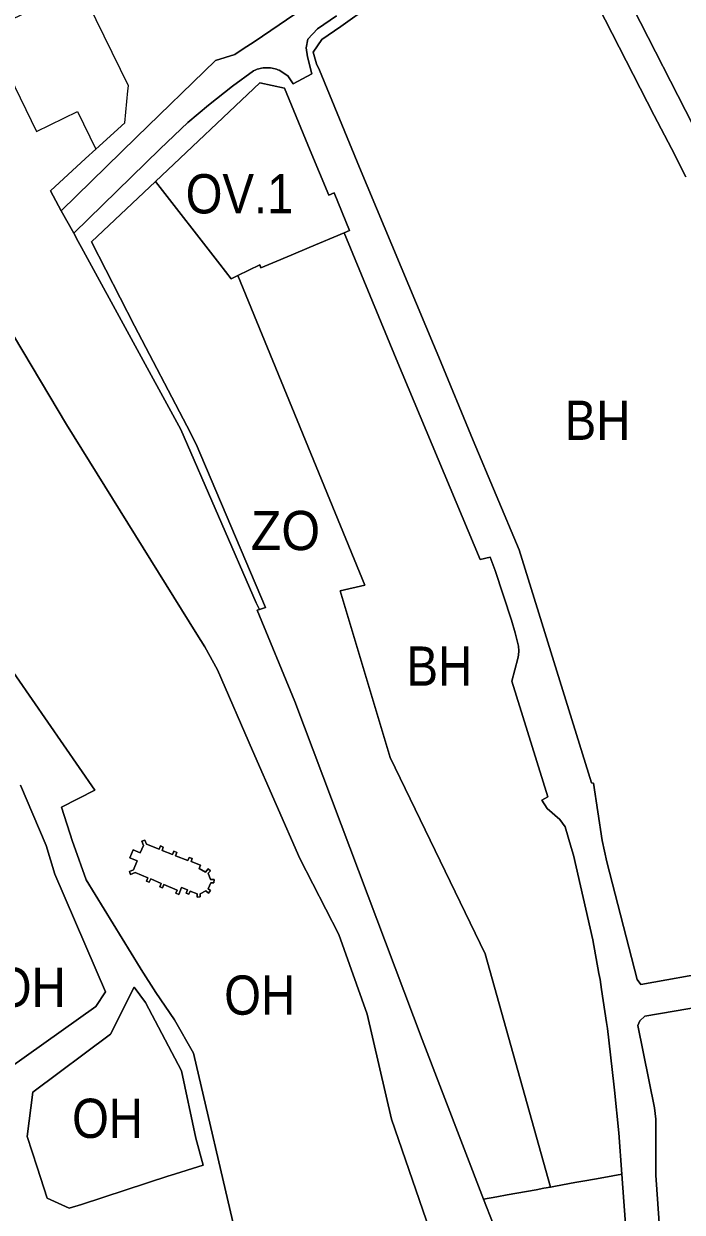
# Model space of a CAD drawing. Extents: x -650451 to -642268, y -1075216 to -1066610.
# Drawn here: x -647556.9 to -647355.8, y -1071464 to -1071100.7 of the extents above; entities that cross this region are included whole.
import ezdxf

# ---------------------------------------------------------------- set-up
doc = ezdxf.new("R2010")
doc.units = 0
doc.header["$LTSCALE"] = 4.8
for name, color, linetype, lineweight in [('1', 7, 'Continuous', 13), ('10', 7, 'Continuous', 13), ('11', 7, 'Continuous', 13), ('15', 7, 'Continuous', 13), ('24', 7, 'Continuous', 13), ('25', 7, 'Continuous', 13), ('42', 7, 'Continuous', 13)]:
    doc.layers.add(name, color=color, linetype=linetype, lineweight=lineweight)
doc.layers.add('62', color=7, linetype='Continuous')

msp = doc.modelspace()

# ---------------------------------------------------------------- linework, layer by layer
at = {"layer": '1'}
for points in [[(-647316.07, -1071202.91), (-647370.76, -1071095.88), (-647373.86, -1071090.07), (-647383.43, -1071070.95), (-647388.51, -1071058.82), (-647387.82, -1071056.14), (-647386.3, -1071054.58), (-647349.67, -1071030.64)], [(-647389.98, -1071078.54), (-647364.3, -1071128.77), (-647359.04, -1071138.83), (-647354.68, -1071147.49)], [(-647345.67, -1071390.27), (-647368.38, -1071394.35), (-647369.51, -1071392.87), (-647378.79, -1071356.84), (-647380.17, -1071350.38), (-647382.83, -1071332.82), (-647383.52, -1071332.79), (-647405.59, -1071261.54), (-647419.59, -1071228.11), (-647430.16, -1071202.64), (-647431.77, -1071198.79), (-647454.33, -1071144.64), (-647466.6, -1071114.88), (-647467.47, -1071112.93), (-647468.47, -1071109.42), (-647465.83, -1071105.54), (-647460.06, -1071101.57), (-647442.36, -1071088.82)], [(-647491.56, -1071177.65), (-647484.85, -1071174.37), (-647484.47, -1071175.32), (-647480.78, -1071173.77), (-647475.25, -1071171.44), (-647469.69, -1071169.11), (-647458.99, -1071164.62)], [(-647458.99, -1071164.62), (-647443.1, -1071203.11), (-647417.48, -1071264.44), (-647414.45, -1071263.72), (-647412.92, -1071267.86), (-647407.95, -1071282.98), (-647406.83, -1071286.84), (-647405.81, -1071290.99), (-647405.67, -1071292.42), (-647405.81, -1071293.71), (-647406, -1071294.73), (-647407.77, -1071301.63), (-647396.78, -1071337.03), (-647398.69, -1071338), (-647397.07, -1071340.54), (-647393.18, -1071343.93), (-647391.57, -1071346.17), (-647389.7, -1071352.48), (-647389.02, -1071354.89), (-647383.11, -1071380.7), (-647381.2, -1071391.04), (-647380.88, -1071392.81), (-647380.41, -1071395.94), (-647378.88, -1071406.02), (-647378.64, -1071407.86), (-647376.66, -1071424.88), (-647376.42, -1071426.67), (-647375.13, -1071439.72), (-647374.2, -1071452.36)], [(-647396.02, -1071456.32), (-647415.97, -1071385.01), (-647445, -1071324.99), (-647460.28, -1071274.02), (-647452.69, -1071272.32), (-647491.56, -1071177.65)], [(-647353.95, -1071567.53), (-647356.2, -1071564.75), (-647356.91, -1071554.11), (-647357.15, -1071550.44), (-647359.03, -1071522.12), (-647359.38, -1071516.88), (-647363.86, -1071452.66), (-647363.83, -1071435.52), (-647364.26, -1071432.14), (-647369.34, -1071406.92), (-647368.74, -1071405.48), (-647367.18, -1071404.12), (-647349.29, -1071400.99)], [(-647374.2, -1071452.36), (-647379.73, -1071453.36), (-647382.59, -1071453.88), (-647385.49, -1071454.41), (-647388.54, -1071454.96), (-647394.45, -1071456.04), (-647396.02, -1071456.32)]]:
    msp.add_lwpolyline(points, dxfattribs=at)
at = {"layer": '10'}
for points in [[(-647565.22, -1071187.4), (-647543.83, -1071223.23), (-647504.01, -1071287.34), (-647501.59, -1071291.15), (-647497.77, -1071298.19), (-647487.02, -1071322.83), (-647472.58, -1071355.91), (-647460.71, -1071379.08), (-647451.96, -1071403.5), (-647444.55, -1071435.57), (-647430.76, -1071475.77), (-647422.68, -1071509.72), (-647416, -1071538.22)], [(-647492.3, -1071470), (-647505.11, -1071415.37), (-647510.84, -1071405.24), (-647516.55, -1071396.79), (-647521.06, -1071389.76), (-647521.32, -1071389.29), (-647537.84, -1071362.41), (-647541.66, -1071351.76), (-647542.01, -1071350.72), (-647545.42, -1071340.16), (-647535.19, -1071335), (-647568.83, -1071286.51), (-647592.65, -1071252.72), (-647607.49, -1071231.68), (-647608.09, -1071228.7), (-647608.04, -1071225.7), (-647607.11, -1071222.78), (-647605.5, -1071220.17)], [(-647557.95, -1071333.44), (-647554.18, -1071342.3), (-647550.12, -1071351.87), (-647547.43, -1071360.71), (-647531.93, -1071396.68), (-647534.94, -1071401.09), (-647561.38, -1071419.94)]]:
    msp.add_lwpolyline(points, dxfattribs=at)
for points in [[(-647523.37, -1071359.34), (-647524.63, -1071359.81), (-647524.28, -1071360.72), (-647522.92, -1071360.2), (-647519.05, -1071361.79), (-647519.46, -1071362.76), (-647518.59, -1071363.1), (-647518.1, -1071362.12), (-647514.97, -1071363.49), (-647515.39, -1071364.49), (-647514.5, -1071364.86), (-647514.09, -1071363.85), (-647510.06, -1071365.53), (-647510.48, -1071366.51), (-647509.58, -1071366.9), (-647508.73, -1071364.78), (-647506.94, -1071365.49), (-647507.29, -1071366.45), (-647506.47, -1071366.76), (-647506.04, -1071365.82), (-647503.99, -1071366.66), (-647503.96, -1071367.67), (-647502.98, -1071367.63), (-647503.01, -1071366.67), (-647501.29, -1071365.73), (-647500.51, -1071366.44), (-647499.87, -1071365.69), (-647500.55, -1071365.1), (-647499.81, -1071363.3), (-647498.84, -1071363.29), (-647498.8, -1071362.34), (-647499.87, -1071362.28), (-647500.57, -1071360.36), (-647499.86, -1071359.67), (-647500.55, -1071359.01), (-647501.43, -1071360.01), (-647503.33, -1071358.95), (-647502.94, -1071357.95), (-647505.79, -1071356.81), (-647505.45, -1071355.86), (-647506.38, -1071355.53), (-647506.75, -1071356.51), (-647510.59, -1071355.01), (-647510.18, -1071354.02), (-647511.1, -1071353.63), (-647511.51, -1071354.65), (-647514.67, -1071353.39), (-647514.29, -1071352.36), (-647515.19, -1071352.03), (-647515.6, -1071353), (-647519.45, -1071351.47), (-647519.95, -1071350.22), (-647520.85, -1071350.56), (-647520.37, -1071351.85), (-647521.31, -1071354.19), (-647523.5, -1071353.25), (-647524.47, -1071355.64), (-647522.28, -1071356.63)], [(-647523.23, -1071395.17), (-647519.72, -1071399.92), (-647508.69, -1071420.74), (-647504.34, -1071441.33), (-647502.09, -1071449.64), (-647512.23, -1071452.75), (-647512.62, -1071452.86), (-647539.31, -1071461.66), (-647543.05, -1071462.76), (-647549.73, -1071459.73), (-647552.85, -1071450.23), (-647555.92, -1071440.87), (-647554.16, -1071427.31), (-647530.41, -1071409.54)]]:
    msp.add_lwpolyline(points, close=True, dxfattribs=at)
at = {"layer": '11'}
for points in [[(-647516.65, -1071148.87), (-647484.84, -1071118.8), (-647477.3, -1071120.38), (-647469.39, -1071139.47), (-647463.76, -1071153.08), (-647462.13, -1071152.39), (-647457.39, -1071163.94), (-647458.99, -1071164.62)], [(-647491.56, -1071177.65), (-647493.58, -1071178.64), (-647497.03, -1071174.18), (-647516.65, -1071148.87)], [(-647458.99, -1071164.62), (-647469.69, -1071169.11), (-647475.25, -1071171.44), (-647480.78, -1071173.77), (-647484.47, -1071175.32), (-647484.85, -1071174.37), (-647491.56, -1071177.65)]]:
    msp.add_lwpolyline(points, dxfattribs=at)
msp.add_lwpolyline([(-647523.37, -1071359.34), (-647522.28, -1071356.63), (-647524.47, -1071355.64), (-647523.5, -1071353.25), (-647521.31, -1071354.19), (-647520.37, -1071351.85), (-647520.85, -1071350.56), (-647519.95, -1071350.22), (-647519.45, -1071351.47), (-647515.6, -1071353), (-647515.19, -1071352.03), (-647514.29, -1071352.36), (-647514.67, -1071353.39), (-647511.51, -1071354.65), (-647511.1, -1071353.63), (-647510.18, -1071354.02), (-647510.59, -1071355.01), (-647506.75, -1071356.51), (-647506.38, -1071355.53), (-647505.45, -1071355.86), (-647505.79, -1071356.81), (-647502.94, -1071357.95), (-647503.33, -1071358.95), (-647501.43, -1071360.01), (-647500.55, -1071359.01), (-647499.86, -1071359.67), (-647500.57, -1071360.36), (-647499.87, -1071362.28), (-647498.8, -1071362.34), (-647498.84, -1071363.29), (-647499.81, -1071363.3), (-647500.55, -1071365.1), (-647499.87, -1071365.69), (-647500.51, -1071366.44), (-647501.29, -1071365.73), (-647503.01, -1071366.67), (-647502.98, -1071367.63), (-647503.96, -1071367.67), (-647503.99, -1071366.66), (-647506.04, -1071365.82), (-647506.47, -1071366.76), (-647507.29, -1071366.45), (-647506.94, -1071365.49), (-647508.73, -1071364.78), (-647509.58, -1071366.9), (-647510.48, -1071366.51), (-647510.06, -1071365.53), (-647514.09, -1071363.85), (-647514.5, -1071364.86), (-647515.39, -1071364.49), (-647514.97, -1071363.49), (-647518.1, -1071362.12), (-647518.59, -1071363.1), (-647519.46, -1071362.76), (-647519.05, -1071361.79), (-647522.92, -1071360.2), (-647524.28, -1071360.72), (-647524.63, -1071359.81)], close=True, dxfattribs=at)
at = {"layer": '15'}
for points in [[(-647364.66, -1071006.25), (-647361.42, -1071004.71), (-647356.96, -1071010.82), (-647356.47, -1071014.98), (-647356.62, -1071017.06), (-647361.56, -1071021.28), (-647392.4, -1071042.15), (-647410.1, -1071054.18), (-647415.14, -1071057.61), (-647469.06, -1071094.28), (-647486.58, -1071106.19), (-647489.86, -1071108.38), (-647492.4, -1071110.08), (-647498.37, -1071111.95), (-647522.5, -1071135.41), (-647545.47, -1071157.86)], [(-647349.67, -1071030.64), (-647386.3, -1071054.58), (-647387.82, -1071056.14), (-647388.51, -1071058.82), (-647383.43, -1071070.95), (-647373.86, -1071090.07), (-647370.76, -1071095.88), (-647316.07, -1071202.91)], [(-647354.68, -1071147.49), (-647359.04, -1071138.83), (-647364.3, -1071128.77), (-647389.98, -1071078.54)], [(-647534.851, -1071139.015), (-647526.04, -1071130.94), (-647525.1, -1071121.25), (-647524.95, -1071119.68), (-647539.817, -1071089.199)], [(-647442.36, -1071088.82), (-647460.06, -1071101.57), (-647465.83, -1071105.54), (-647468.47, -1071109.42), (-647467.47, -1071112.93), (-647466.6, -1071114.88), (-647454.33, -1071144.64), (-647431.77, -1071198.79), (-647430.16, -1071202.64), (-647419.59, -1071228.11), (-647405.59, -1071261.54), (-647383.52, -1071332.79), (-647382.83, -1071332.82), (-647380.17, -1071350.38), (-647378.79, -1071356.84), (-647369.51, -1071392.87), (-647368.38, -1071394.35), (-647345.67, -1071390.27)], [(-647541.66, -1071164.75), (-647515.26, -1071138.89), (-647506.78, -1071130.92), (-647500.44, -1071125.54), (-647493.16, -1071119.77), (-647486.76, -1071115.13), (-647486, -1071114.76), (-647485.58, -1071114.61), (-647485.149, -1071114.479), (-647484.709, -1071114.368), (-647484.262, -1071114.278), (-647483.809, -1071114.209), (-647483.352, -1071114.162), (-647482.892, -1071114.138), (-647482.43, -1071114.137), (-647481.969, -1071114.158), (-647481.51, -1071114.201), (-647481.055, -1071114.267), (-647480.605, -1071114.355), (-647480.163, -1071114.464), (-647479.728, -1071114.593), (-647479.304, -1071114.742), (-647478.89, -1071114.91), (-647476.29, -1071116.6), (-647474.6, -1071119.05), (-647468.9, -1071115.97), (-647470.21, -1071110.77), (-647470.6, -1071108.01), (-647470.17, -1071105.39), (-647467.21, -1071102.22), (-647461.39, -1071098.23)], [(-647458.99, -1071164.62), (-647457.39, -1071163.94), (-647462.13, -1071152.39), (-647463.76, -1071153.08), (-647469.39, -1071139.47), (-647477.3, -1071120.38), (-647484.84, -1071118.8), (-647516.65, -1071148.87)], [(-647545.47, -1071157.86), (-647548.7, -1071151.72), (-647538.02, -1071141.92), (-647534.851, -1071139.015)], [(-647516.65, -1071148.87), (-647536.2, -1071167.35), (-647523.09, -1071193.08), (-647507.14, -1071223.62), (-647504.27, -1071229.17), (-647483.04, -1071279.11), (-647484.9, -1071279.73)], [(-647484.9, -1071279.73), (-647485.9, -1071277.7), (-647508.98, -1071224.74), (-647539.25, -1071169.11), (-647540.27, -1071167.26), (-647541.66, -1071164.75)], [(-647374.2, -1071452.36), (-647375.13, -1071439.72), (-647376.42, -1071426.67), (-647376.66, -1071424.88), (-647378.64, -1071407.86), (-647378.88, -1071406.02), (-647380.41, -1071395.94), (-647380.88, -1071392.81), (-647381.2, -1071391.04), (-647383.11, -1071380.7), (-647389.02, -1071354.89), (-647389.7, -1071352.48), (-647391.57, -1071346.17), (-647393.18, -1071343.93), (-647397.07, -1071340.54), (-647398.69, -1071338), (-647396.78, -1071337.03), (-647407.77, -1071301.63), (-647406, -1071294.73), (-647405.81, -1071293.71), (-647405.67, -1071292.42), (-647405.81, -1071290.99), (-647406.83, -1071286.84), (-647407.95, -1071282.98), (-647412.92, -1071267.86), (-647414.45, -1071263.72), (-647417.48, -1071264.44), (-647443.1, -1071203.11), (-647458.99, -1071164.62)], [(-647605.5, -1071220.17), (-647607.11, -1071222.78), (-647608.04, -1071225.7), (-647608.09, -1071228.7), (-647607.49, -1071231.68), (-647592.65, -1071252.72), (-647568.83, -1071286.51), (-647535.19, -1071335), (-647545.42, -1071340.16), (-647542.01, -1071350.72), (-647541.66, -1071351.76), (-647537.84, -1071362.41), (-647521.32, -1071389.29), (-647521.06, -1071389.76), (-647516.55, -1071396.79), (-647510.84, -1071405.24), (-647505.11, -1071415.37), (-647492.3, -1071470), (-647498.8, -1071471.94)], [(-647561.38, -1071419.94), (-647534.94, -1071401.09), (-647531.93, -1071396.68), (-647547.43, -1071360.71), (-647550.12, -1071351.87), (-647554.18, -1071342.3), (-647557.95, -1071333.44)], [(-647349.29, -1071400.99), (-647367.18, -1071404.12), (-647368.74, -1071405.48), (-647369.34, -1071406.92), (-647364.26, -1071432.14), (-647363.83, -1071435.52), (-647363.86, -1071452.66), (-647359.38, -1071516.88), (-647359.03, -1071522.12), (-647357.15, -1071550.44), (-647356.91, -1071554.11), (-647356.2, -1071564.75), (-647353.95, -1071567.53)], [(-647377.13, -1071562.56), (-647365.91, -1071564.81), (-647368.26, -1071532.99), (-647374.2, -1071452.36)]]:
    msp.add_lwpolyline(points, dxfattribs=at)
msp.add_lwpolyline([(-647523.23, -1071395.17), (-647530.41, -1071409.54), (-647554.16, -1071427.31), (-647555.92, -1071440.87), (-647552.85, -1071450.23), (-647549.73, -1071459.73), (-647543.05, -1071462.76), (-647539.31, -1071461.66), (-647512.62, -1071452.86), (-647512.23, -1071452.75), (-647502.09, -1071449.64), (-647504.34, -1071441.33), (-647508.69, -1071420.74), (-647519.72, -1071399.92)], close=True, dxfattribs=at)
at = {"layer": '24'}
msp.add_line((-647541.66, -1071164.75), (-647545.47, -1071157.86), dxfattribs=at)
for points in [[(-647545.47, -1071157.86), (-647522.5, -1071135.41), (-647498.37, -1071111.95), (-647492.4, -1071110.08), (-647489.86, -1071108.38), (-647486.58, -1071106.19), (-647469.06, -1071094.28), (-647415.14, -1071057.61), (-647410.1, -1071054.18), (-647392.4, -1071042.15), (-647361.56, -1071021.28), (-647356.62, -1071017.06), (-647356.47, -1071014.98), (-647356.96, -1071010.82), (-647361.42, -1071004.71), (-647364.66, -1071006.25)], [(-647461.39, -1071098.23), (-647467.21, -1071102.22), (-647470.17, -1071105.39), (-647470.6, -1071108.01), (-647470.21, -1071110.77), (-647468.9, -1071115.97), (-647474.6, -1071119.05), (-647476.29, -1071116.6), (-647478.89, -1071114.91), (-647479.304, -1071114.742), (-647479.728, -1071114.593), (-647480.163, -1071114.464), (-647480.605, -1071114.355), (-647481.055, -1071114.267), (-647481.51, -1071114.201), (-647481.969, -1071114.158), (-647482.43, -1071114.137), (-647482.892, -1071114.138), (-647483.352, -1071114.162), (-647483.809, -1071114.209), (-647484.262, -1071114.278), (-647484.709, -1071114.368), (-647485.149, -1071114.479), (-647485.58, -1071114.61), (-647486, -1071114.76), (-647486.76, -1071115.13), (-647493.16, -1071119.77), (-647500.44, -1071125.54), (-647506.78, -1071130.92), (-647515.26, -1071138.89), (-647541.66, -1071164.75)], [(-647396.02, -1071456.32), (-647394.45, -1071456.04), (-647388.54, -1071454.96), (-647385.49, -1071454.41), (-647382.59, -1071453.88), (-647379.73, -1071453.36), (-647374.2, -1071452.36)], [(-647374.2, -1071452.36), (-647368.26, -1071532.99), (-647365.91, -1071564.81), (-647377.13, -1071562.56)], [(-647416.42, -1071460.03), (-647412.36, -1071459.29), (-647409.26, -1071458.73), (-647403.35, -1071457.65), (-647400.4, -1071457.12), (-647398.057, -1071456.69), (-647396.02, -1071456.32)], [(-647377.13, -1071562.56), (-647379.49, -1071550.89), (-647388.29, -1071528.41), (-647398.64, -1071501.96), (-647413.54, -1071467.53), (-647416.42, -1071460.03)]]:
    msp.add_lwpolyline(points, dxfattribs=at)
at = {"layer": '25'}
for points in [[(-647539.817, -1071089.199), (-647568.01, -1071102.98), (-647553.01, -1071133.68), (-647540.48, -1071127.55), (-647534.851, -1071139.015)], [(-647534.851, -1071139.015), (-647538.02, -1071141.92), (-647548.7, -1071151.72), (-647545.47, -1071157.86), (-647541.66, -1071164.75)], [(-647541.66, -1071164.75), (-647540.27, -1071167.26), (-647539.25, -1071169.11), (-647508.98, -1071224.74), (-647485.9, -1071277.7), (-647484.9, -1071279.73)], [(-647416, -1071538.22), (-647422.68, -1071509.72), (-647430.76, -1071475.77), (-647444.55, -1071435.57), (-647451.96, -1071403.5), (-647460.71, -1071379.08), (-647472.58, -1071355.91), (-647487.02, -1071322.83), (-647497.77, -1071298.19), (-647501.59, -1071291.15), (-647504.01, -1071287.34), (-647543.83, -1071223.23), (-647565.22, -1071187.4)], [(-647484.9, -1071279.73), (-647485.58, -1071279.95), (-647474.15, -1071307.9), (-647471.19, -1071315.76), (-647435.19, -1071411.22), (-647416.42, -1071460.03)], [(-647416.42, -1071460.03), (-647413.54, -1071467.53), (-647398.64, -1071501.96), (-647388.29, -1071528.41), (-647379.49, -1071550.89), (-647377.13, -1071562.56)]]:
    msp.add_lwpolyline(points, dxfattribs=at)
at = {"layer": '42'}
for points in [[(-647484.9, -1071279.73), (-647483.04, -1071279.11), (-647504.27, -1071229.17), (-647507.14, -1071223.62), (-647523.09, -1071193.08), (-647536.2, -1071167.35), (-647516.65, -1071148.87)], [(-647516.65, -1071148.87), (-647497.03, -1071174.18), (-647493.58, -1071178.64), (-647491.56, -1071177.65)], [(-647491.56, -1071177.65), (-647452.69, -1071272.32), (-647460.28, -1071274.02), (-647445, -1071324.99), (-647415.97, -1071385.01), (-647396.02, -1071456.32)], [(-647416.42, -1071460.03), (-647435.19, -1071411.22), (-647471.19, -1071315.76), (-647474.15, -1071307.9), (-647485.58, -1071279.95), (-647484.9, -1071279.73)], [(-647396.02, -1071456.32), (-647398.057, -1071456.69), (-647400.4, -1071457.12), (-647403.35, -1071457.65), (-647409.26, -1071458.73), (-647412.36, -1071459.29), (-647416.42, -1071460.03)]]:
    msp.add_lwpolyline(points, dxfattribs=at)

# ---------------------------------------------------------------- texts
at = {"layer": '62'}
for s, width, p in [('OV.1', 0.9, (-647507.45, -1071158.674)), ('BH', 0.9, (-647391.666, -1071227.911)), ('ZO', 0.95, (-647487.537, -1071261.606)), ('BH', 0.9, (-647439.98, -1071303.06)), ('OH', 0.9, (-647565.757, -1071401.249)), ('OH', 0.9, (-647495.683, -1071403.624)), ('OH', 0.9, (-647542.151, -1071441.295))]:
    msp.add_text(s, height=12, dxfattribs=dict(at, width=width)).set_placement(p)

doc.saveas('drawing.dxf')
